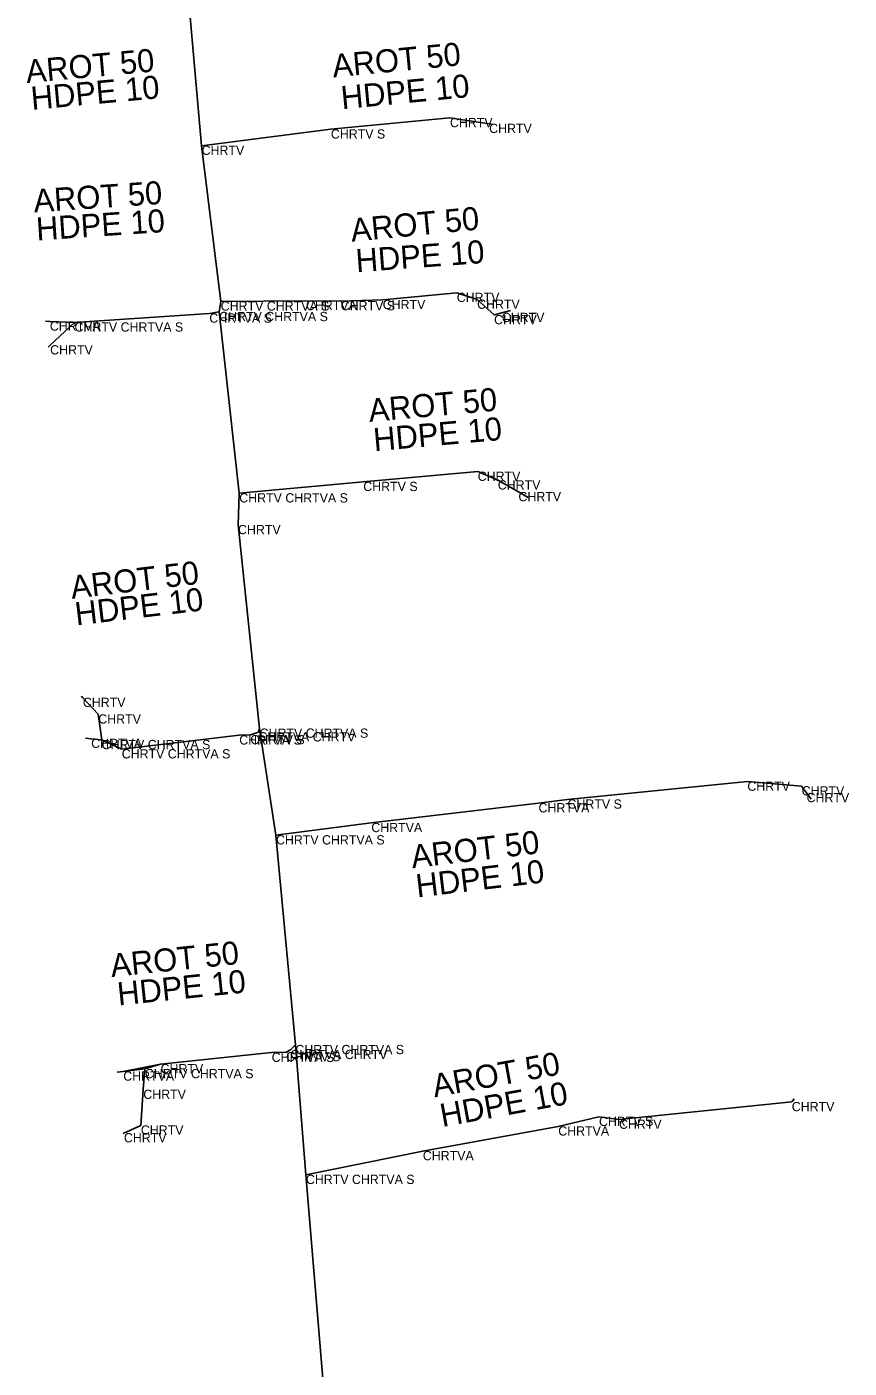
# Model space of a CAD drawing. Extents: x -651943 to -618711, y -1138561 to -1100552.
# Drawn here: x -641006.1 to -640979.44, y -1114680.83 to -1114637.34 of the extents above; entities that cross this region are included whole.
import ezdxf

# ---------------------------------------------------------------- set-up
doc = ezdxf.new("R2010")
doc.units = 0
for name, color, linetype in [('KT optika', 7, 'Continuous'), ('KT trasa', 7, 'Continuous'), ('KT zařízení', 7, 'Continuous')]:
    doc.layers.add(name, color=color, linetype=linetype)

msp = doc.modelspace()

# ---------------------------------------------------------------- linework, layer by layer
at = {"layer": 'KT optika'}
for p, q in [((-641000.43, -1114641.19), (-641000.85, -1114636.53)), ((-640996.24, -1114640.66), (-640992.38, -1114640.29)), ((-640996.24, -1114640.66), (-641000.43, -1114641.19)), ((-640999.81, -1114646.24), (-641000.43, -1114641.19)), ((-640994.56, -1114646.19), (-640992.16, -1114645.96)), ((-640992.16, -1114645.96), (-640991.5, -1114646.18)), ((-640991.5, -1114646.18), (-640990.95, -1114646.68)), ((-641000.18, -1114646.63), (-641004.55, -1114646.92)), ((-640999.86, -1114646.58), (-641000.18, -1114646.63)), ((-640999.86, -1114646.58), (-640999.81, -1114646.24)), ((-640999.21, -1114652.46), (-640999.86, -1114646.58)), ((-640999.81, -1114646.24), (-640997.05, -1114646.22)), ((-640995.19, -1114652.09), (-640991.48, -1114651.76)), ((-640991.48, -1114651.76), (-640990.83, -1114652.04)), ((-640999.21, -1114652.46), (-640995.19, -1114652.09)), ((-640999.25, -1114653.49), (-640999.21, -1114652.46)), ((-640998.55, -1114660.09), (-640999.25, -1114653.49)), ((-641003.67, -1114660.46), (-641003.78, -1114659.63)), ((-640998.55, -1114660.09), (-640998.59, -1114660.21)), ((-640998.02, -1114663.55), (-640998.55, -1114660.09)), ((-641003.02, -1114660.76), (-641003.67, -1114660.46)), ((-640999.21, -1114660.31), (-641003.02, -1114660.76)), ((-640998.85, -1114660.3), (-640999.21, -1114660.31)), ((-640998.59, -1114660.21), (-640998.85, -1114660.3)), ((-640988.57, -1114662.39), (-640982.74, -1114661.81)), ((-640982.74, -1114661.81), (-640980.98, -1114661.96)), ((-640994.93, -1114663.15), (-640989.51, -1114662.51)), ((-640989.51, -1114662.51), (-640988.57, -1114662.39)), ((-640998.02, -1114663.55), (-640994.93, -1114663.15)), ((-640997.39, -1114670.35), (-640998.02, -1114663.55)), ((-640997.55, -1114670.51), (-640997.69, -1114670.58)), ((-640997.39, -1114670.35), (-640997.55, -1114670.51)), ((-640997.05, -1114674.56), (-640997.39, -1114670.35)), ((-641001.76, -1114670.97), (-641002.27, -1114671.13)), ((-640998.16, -1114670.6), (-641001.76, -1114670.97)), ((-640997.69, -1114670.58), (-640998.16, -1114670.6)), ((-641002.27, -1114671.13), (-641002.32, -1114671.8)), ((-641002.32, -1114671.8), (-641002.4, -1114672.96)), ((-640986.9, -1114672.77), (-640981.3, -1114672.2)), ((-640981.3, -1114672.2), (-640981.22, -1114672.1)), ((-640988.87, -1114672.99), (-640987.55, -1114672.68)), ((-640987.55, -1114672.68), (-640986.9, -1114672.77)), ((-640993.26, -1114673.79), (-640988.87, -1114672.99)), ((-640997.05, -1114674.56), (-640993.26, -1114673.79)), ((-640996.37, -1114682.73), (-640997.05, -1114674.56))]:
    msp.add_line(p, q, dxfattribs=at)
for points in [[(-640992.38, -1114640.29), (-640991.11, -1114640.48), (-640990.979, -1114640.5)], [(-640997.05, -1114646.22), (-640995.92, -1114646.23), (-640994.56, -1114646.19)], [(-640990.95, -1114646.68), (-640990.7, -1114646.61), (-640990.423, -1114646.532)], [(-641004.55, -1114646.92), (-641005.35, -1114646.89), (-641005.486, -1114646.885)], [(-641004.55, -1114646.92), (-641005.34, -1114647.66), (-641005.407, -1114647.723)], [(-640990.83, -1114652.04), (-640990.16, -1114652.42), (-640989.848, -1114652.597)], [(-641003.78, -1114659.63), (-641004.28, -1114659.09), (-641004.324, -1114659.042)], [(-641003.67, -1114660.46), (-641004.01, -1114660.42), (-641004.197, -1114660.398)], [(-640980.98, -1114661.96), (-640980.82, -1114662.18), (-640980.672, -1114662.383)], [(-641002.27, -1114671.13), (-641002.97, -1114671.21), (-641003.171, -1114671.233)], [(-641002.4, -1114672.96), (-641002.95, -1114673.21), (-641002.972, -1114673.22)]]:
    msp.add_lwpolyline(points, dxfattribs=at)
at = {"layer": 'KT trasa'}
for p, q in [((-641000.43, -1114641.19), (-641000.85, -1114636.53)), ((-640996.24, -1114640.66), (-640992.38, -1114640.29)), ((-640996.24, -1114640.66), (-641000.43, -1114641.19)), ((-640999.81, -1114646.24), (-641000.43, -1114641.19)), ((-640994.56, -1114646.19), (-640992.16, -1114645.96)), ((-640992.16, -1114645.96), (-640991.5, -1114646.18)), ((-640991.5, -1114646.18), (-640990.95, -1114646.68)), ((-641000.18, -1114646.63), (-641004.55, -1114646.92)), ((-640999.86, -1114646.58), (-641000.18, -1114646.63)), ((-640999.86, -1114646.58), (-640999.81, -1114646.24)), ((-640999.21, -1114652.46), (-640999.86, -1114646.58)), ((-640999.81, -1114646.24), (-640997.05, -1114646.22)), ((-640995.19, -1114652.09), (-640991.48, -1114651.76)), ((-640991.48, -1114651.76), (-640990.83, -1114652.04)), ((-640999.21, -1114652.46), (-640995.19, -1114652.09)), ((-640999.25, -1114653.49), (-640999.21, -1114652.46)), ((-640998.55, -1114660.09), (-640999.25, -1114653.49)), ((-641003.67, -1114660.46), (-641003.78, -1114659.63)), ((-640998.55, -1114660.09), (-640998.59, -1114660.21)), ((-640998.02, -1114663.55), (-640998.55, -1114660.09)), ((-641003.02, -1114660.76), (-641003.67, -1114660.46)), ((-640999.21, -1114660.31), (-641003.02, -1114660.76)), ((-640998.85, -1114660.3), (-640999.21, -1114660.31)), ((-640998.59, -1114660.21), (-640998.85, -1114660.3)), ((-640988.57, -1114662.39), (-640982.74, -1114661.81)), ((-640982.74, -1114661.81), (-640980.98, -1114661.96)), ((-640994.93, -1114663.15), (-640989.51, -1114662.51)), ((-640989.51, -1114662.51), (-640988.57, -1114662.39)), ((-640998.02, -1114663.55), (-640994.93, -1114663.15)), ((-640997.39, -1114670.35), (-640998.02, -1114663.55)), ((-640997.55, -1114670.51), (-640997.69, -1114670.58)), ((-640997.39, -1114670.35), (-640997.55, -1114670.51)), ((-640997.05, -1114674.56), (-640997.39, -1114670.35)), ((-641001.76, -1114670.97), (-641002.27, -1114671.13)), ((-640998.16, -1114670.6), (-641001.76, -1114670.97)), ((-640997.69, -1114670.58), (-640998.16, -1114670.6)), ((-641002.27, -1114671.13), (-641002.32, -1114671.8)), ((-641002.32, -1114671.8), (-641002.4, -1114672.96)), ((-640986.9, -1114672.77), (-640981.3, -1114672.2)), ((-640981.3, -1114672.2), (-640981.22, -1114672.1)), ((-640988.87, -1114672.99), (-640987.55, -1114672.68)), ((-640987.55, -1114672.68), (-640986.9, -1114672.77)), ((-640993.26, -1114673.79), (-640988.87, -1114672.99)), ((-640997.05, -1114674.56), (-640993.26, -1114673.79)), ((-640996.37, -1114682.73), (-640997.05, -1114674.56))]:
    msp.add_line(p, q, dxfattribs=at)
for points in [[(-640992.38, -1114640.29), (-640991.11, -1114640.48), (-640990.979, -1114640.5)], [(-640997.05, -1114646.22), (-640995.92, -1114646.23), (-640994.56, -1114646.19)], [(-640990.95, -1114646.68), (-640990.7, -1114646.61), (-640990.423, -1114646.532)], [(-641004.55, -1114646.92), (-641005.35, -1114646.89), (-641005.486, -1114646.885)], [(-641004.55, -1114646.92), (-641005.34, -1114647.66), (-641005.407, -1114647.723)], [(-640990.83, -1114652.04), (-640990.16, -1114652.42), (-640989.848, -1114652.597)], [(-641003.78, -1114659.63), (-641004.28, -1114659.09), (-641004.324, -1114659.042)], [(-641003.67, -1114660.46), (-641004.01, -1114660.42), (-641004.197, -1114660.398)], [(-640980.98, -1114661.96), (-640980.82, -1114662.18), (-640980.672, -1114662.383)], [(-641002.27, -1114671.13), (-641002.97, -1114671.21), (-641003.171, -1114671.233)], [(-641002.4, -1114672.96), (-641002.95, -1114673.21), (-641002.972, -1114673.22)]]:
    msp.add_lwpolyline(points, dxfattribs=at)
at = {"layer": 'KT zařízení'}
for points in [[(-640996.37, -1114682.73), (-640997.05, -1114674.56), (-640997.39, -1114670.35), (-640998.02, -1114663.55), (-640998.55, -1114660.09), (-640999.25, -1114653.49), (-640999.21, -1114652.46), (-640999.86, -1114646.58), (-640999.81, -1114646.24), (-641000.43, -1114641.19), (-641000.85, -1114636.53)], [(-641000.43, -1114641.19), (-640996.24, -1114640.66), (-640992.38, -1114640.29), (-640991.11, -1114640.48), (-640990.979, -1114640.5)], [(-640999.81, -1114646.24), (-640997.05, -1114646.22), (-640995.92, -1114646.23), (-640994.56, -1114646.19), (-640992.16, -1114645.96), (-640991.5, -1114646.18), (-640990.95, -1114646.68), (-640990.7, -1114646.61), (-640990.423, -1114646.532)], [(-641000.18, -1114646.63), (-641004.55, -1114646.92), (-641005.35, -1114646.89), (-641005.486, -1114646.885)], [(-641005.407, -1114647.723), (-641005.34, -1114647.66), (-641004.55, -1114646.92)], [(-640999.21, -1114652.46), (-640995.19, -1114652.09), (-640991.48, -1114651.76), (-640990.83, -1114652.04), (-640990.16, -1114652.42), (-640989.848, -1114652.597)], [(-640998.85, -1114660.3), (-640999.21, -1114660.31), (-641003.02, -1114660.76), (-641003.67, -1114660.46), (-641003.78, -1114659.63), (-641004.28, -1114659.09)], [(-640998.02, -1114663.55), (-640994.93, -1114663.15), (-640989.51, -1114662.51), (-640988.57, -1114662.39), (-640982.74, -1114661.81), (-640980.98, -1114661.96), (-640980.82, -1114662.18), (-640980.672, -1114662.383)], [(-640997.69, -1114670.58), (-640998.16, -1114670.6), (-641001.76, -1114670.97), (-641002.97, -1114671.21), (-641003.171, -1114671.233)], [(-641002.27, -1114671.13), (-641002.32, -1114671.8), (-641002.4, -1114672.96), (-641002.95, -1114673.21)], [(-640997.05, -1114674.56), (-640993.26, -1114673.79), (-640988.87, -1114672.99), (-640987.55, -1114672.68), (-640986.9, -1114672.77), (-640981.3, -1114672.2)]]:
    msp.add_lwpolyline(points, dxfattribs=at)

# ---------------------------------------------------------------- texts
for s, rotation, p in [('AROT 50', 5.4754, (-640996.163, -1114638.98)), ('AROT 50', 5.1814, (-641006.098, -1114639.16)), ('HDPE 10', 5.2087, (-641005.932, -1114640.03)), ('HDPE 10', 5.4754, (-640995.879, -1114640.01)), ('AROT 50', 3.7967, (-641005.858, -1114643.355)), ('AROT 50', 5.4741, (-640995.565, -1114644.306)), ('HDPE 10', 3.7967, (-641005.772, -1114644.266)), ('HDPE 10', 4.1559, (-640995.41, -1114645.295)), ('AROT 50', 5.083, (-640994.988, -1114650.15)), ('HDPE 10', 5.083, (-640994.832, -1114651.099)), ('AROT 50', 6.736, (-641004.635, -1114655.886)), ('HDPE 10', 6.736, (-641004.493, -1114656.748)), ('AROT 50', 6.7344, (-640993.599, -1114664.622)), ('HDPE 10', 6.7344, (-640993.441, -1114665.57)), ('AROT 50', 5.8681, (-641003.348, -1114668.15)), ('HDPE 10', 5.8681, (-641003.126, -1114669.074)), ('AROT 50', 10.3278, (-640992.879, -1114672.052)), ('HDPE 10', 10.3278, (-640992.628, -1114673.014))]:
    msp.add_text(s, height=0.75, rotation=rotation, dxfattribs=at).set_placement(p)
for s, p in [('CHRTV', (-640992.38, -1114640.59)), ('CHRTV', (-640991.11, -1114640.78)), ('CHRTV S', (-640996.24, -1114640.96)), ('CHRTV', (-641000.43, -1114641.49)), ('CHRTV', (-640994.56, -1114646.49)), ('CHRTV', (-640992.16, -1114646.26)), ('CHRTV', (-640991.5, -1114646.48)), ('CHRTVA S', (-641000.18, -1114646.93)), ('CHRTV CHRTVA S', (-640999.86, -1114646.88)), ('CHRTV CHRTVA S', (-640999.81, -1114646.54)), ('CHRTVA', (-640997.05, -1114646.52)), ('CHRTV S', (-640995.92, -1114646.53)), ('CHRTV', (-640990.7, -1114646.91)), ('CHRTVA', (-641005.35, -1114647.19)), ('CHRTV CHRTVA S', (-641004.55, -1114647.22)), ('CHRTV', (-640990.95, -1114646.98)), ('CHRTV', (-641005.34, -1114647.96)), ('CHRTV', (-640991.48, -1114652.06)), ('CHRTV S', (-640995.19, -1114652.39)), ('CHRTV', (-640990.83, -1114652.34)), ('CHRTV CHRTVA S', (-640999.21, -1114652.76)), ('CHRTV', (-640990.16, -1114652.72)), ('CHRTV', (-640999.25, -1114653.79)), ('CHRTV', (-641004.28, -1114659.39)), ('CHRTV', (-641003.78, -1114659.93)), ('CHRTV CHRTVA S', (-640998.55, -1114660.39)), ('CHRTVA', (-641004.01, -1114660.72)), ('CHRTV CHRTVA S', (-641003.67, -1114660.76)), ('CHRTVA S', (-640999.21, -1114660.61)), ('CHRTV S', (-640998.85, -1114660.6)), ('CHRTVA CHRTV', (-640998.59, -1114660.51)), ('CHRTV CHRTVA S', (-641003.02, -1114661.06)), ('CHRTV', (-640982.74, -1114662.11)), ('CHRTV', (-640980.98, -1114662.26)), ('CHRTV', (-640980.82, -1114662.48)), ('CHRTVA', (-640989.51, -1114662.81)), ('CHRTV S', (-640988.57, -1114662.69)), ('CHRTVA', (-640994.93, -1114663.45)), ('CHRTV CHRTVA S', (-640998.02, -1114663.85)), ('CHRTVA CHRTV', (-640997.55, -1114670.81)), ('CHRTV CHRTVA S', (-640997.39, -1114670.65)), ('CHRTV', (-641001.76, -1114671.27)), ('CHRTVA S', (-640998.16, -1114670.9)), ('CHRTV S', (-640997.69, -1114670.88)), ('CHRTVA', (-641002.97, -1114671.51)), ('CHRTV CHRTVA S', (-641002.27, -1114671.43)), ('CHRTV', (-641002.32, -1114672.1)), ('CHRTV', (-640981.3, -1114672.5)), ('CHRTV S', (-640987.55, -1114672.98)), ('CHRTV', (-641002.4, -1114673.26)), ('CHRTVA', (-640988.87, -1114673.29)), ('CHRTV', (-640986.9, -1114673.07)), ('CHRTV', (-641002.95, -1114673.51)), ('CHRTVA', (-640993.26, -1114674.09)), ('CHRTV CHRTVA S', (-640997.05, -1114674.86))]:
    msp.add_text(s, height=0.3, dxfattribs=at).set_placement(p)

doc.saveas('drawing.dxf')
